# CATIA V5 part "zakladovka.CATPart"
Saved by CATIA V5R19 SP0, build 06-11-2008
Part number: zakladovka
Bounding box of the stored display mesh (mm): x -47.99 to 396.99, y -48 to 48, z -5 to 25
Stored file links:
  C:\Users\Jozef Drozd\Desktop\zostava\zakladovka.CATPart
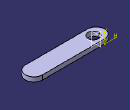
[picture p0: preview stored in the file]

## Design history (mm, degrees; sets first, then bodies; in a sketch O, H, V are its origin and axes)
Body1 (main body)
  Sketch1 on xy-plane, origin (0, 0, 0), H (1, 0, 0), V (0, 1, 0)
    construction line L1 (0, 0) -> (349, 0)
    line L2 (0, 48) -> (349, 48)
    line L3 (349, -48) -> (0, -48)
    arc A1 centre (349, 0) radius 48 from (349, 48) to (349, -48) cw
    arc A2 centre (0, 0) radius 48 from (0, -48) to (0, 48) cw
    distance L1 L2 = 48
    horizontal: L1 H
    tangency: A1 L2, A2 L2, A1 L3, A2 L3
  Pad1: profile Sketch1, direction (0, 0, 1), length 25
  DatumCurve1
  DatumCurve2
  Sketch2 on end face of Pad1, origin (0, 0, 25), H (1, 0, 0), V (0, 1, 0)
    circle A1 centre (15.409, 0) radius 30.0167
    point P1 (15.409, 0)
    reference projected arc E1 centre (0, 0) radius 48 from (0, 48) to (0, -48) ccw from edge [face of Pad1 from Sketch1.A2 | end face of Pad1]
    distance P1 E1 = 63.409
    coincidence: P1 H
  Pocket1: profile Sketch2, direction (0, 0, -1), length 25
  DatumPoint1
  DatumCurve3
  Sketch3 on face of Pad1 from Sketch1.L2, origin (0, 48, 0), H (-1, 0, 0), V (0, 0, 1)
    reference projected line E1 (-229.14, -5) -> (-229.14, -24) from edge of DatumCurve3
    reference projected point E2 (-349, 25) from vertex [face of Pad1 from Sketch1.L2 | end face of Pad1 | face of Pad1 from Sketch1.A1]
    distance E1 E2 = 119.86 (reference)
  Sketch4 on end face of Pad1, origin (0, 0, 25), H (1, 0, 0), V (0, 1, 0)
    line L1 (229.14, 41) -> (232.14, 41)
    line L2 (232.14, 41) -> (232.14, -44)
    line L3 (232.14, -44) -> (229.14, -44)
    line L4 (229.14, -44) -> (229.14, 41)
    reference projected point E1 (349, 48) from vertex [face of Pad1 from Sketch1.L2 | end face of Pad1 | face of Pad1 from Sketch1.A1]
    distance L4 E1 = 119.86
    horizontal: L1 H, L3 H
    vertical: L2 V, L4 V
  Pad2: profile Sketch4, direction (0, 0, -1), length 30
  Sketch5 on end face of Pad1, origin (0, 0, 25), H (1, 0, 0), V (0, 1, 0)
    line L1 (270, 31) -> (273, 31)
    line L2 (273, 31) -> (273, -36)
    line L3 (273, -36) -> (270, -36)
    line L4 (270, -36) -> (270, 31)
    reference projected point E1 (349, 48) from vertex [face of Pad1 from Sketch1.L2 | end face of Pad1 | face of Pad1 from Sketch1.A1]
    distance L4 E1 = 79
    horizontal: L1 H, L3 H
    vertical: L2 V, L4 V
  Pad3: profile Sketch5, direction (0, 0, -1), length 30
  Sketch6 on start face of Pad1, origin (0, 0, 0), H (1, 0, 0), V (0, -1, 0)
    reference projected line E1 (229.14, -22) -> (229.14, 22) from edge of DatumCurve1
    reference projected line E2 (244.14, -20) -> (244.14, -10) from edge of DatumCurve2
    reference projected line E3 (0, 48) -> (349, 48) from edge [start face of Pad1 | face of Pad1 from Sketch1.L3]
    reference projected line E4 (0, 48) -> (349, 48) from edge [start face of Pad1 | face of Pad1 from Sketch1.L3]
    distance E1 E2 = 15 (reference)
    distance E3 E4 = 0 (reference)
